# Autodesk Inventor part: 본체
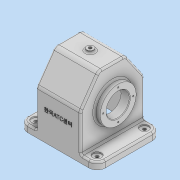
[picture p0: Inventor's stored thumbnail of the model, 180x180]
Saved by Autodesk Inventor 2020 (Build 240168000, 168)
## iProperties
Created: 2022-12
Part Number: 본체
Material: 일반
Document SubType Name: Modeling
Designer: 1강의실14
Density: 1 g/cm^3
Appearance: 기본값
Mass: 347.033 g
Surface Area: 1065.53 cm^2
Volume: 347.033 cm^3
Author: 1강의실14
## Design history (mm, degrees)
sketch "스케치1"
  geometry: L1 (67, -55)-(-67, -55); L2 (-67, -55)-(-67, 55); L3 (-67, 55)-(67, 55); L4 (67, 55)-(67, -55); L5 (67, -55)-(-67, 55); L6 (-67, -55)-(67, 55); 1 further point
  constraints: 12 end point, 2 midpoint, 2 parallel, 1 horizontal, 1 perpendicular
  dimensions: "d0" = 134 distance of L2.end L3.end; "d1" = 110 distance of L1.end L2.end
extrude "돌출1" new body sketch "스케치1" distance "d2" = 12; taper "d3" = 0 deg
fillet "모깎기1" dims "d4" = 14
sketch "스케치2"
  geometry: A1 r 14 centre (-53, -41) between (-67, -41) and (-53, -55) reference; A2 r 14 centre (-53, 41) between (-53, 55) and (-67, 41) reference; A3 r 14 centre (53, -41) between (53, -55) and (67, -41) reference; A4 r 14 centre (53, 41) between (67, 41) and (53, 55) reference; 5 further points
  constraints: 4 coincident
hole "구멍1" sketch "스케치2" at (-53, -41), (-53, 41), (53, -41), (53, 41) diameter "d5" = 5.5; stored, may be unused: countersink angle "d9" = 90 deg, drill point angle "d11" = 118 deg; dims "d6" = 30, "d7" = 15, "d8" = 2, "d10" = 8
sketch "스케치3"
  geometry: L1 (55, 0)-(55, 12) reference; L2 (-55, 12)-(-55, 0) reference; L3 (55, 12)-(55, 77); L4 (55, 77)-(23.491, 122); L5 (23.491, 122)-(-23.491, 122); L6 (-23.491, 122)-(-55, 77); L7 (-55, 77)-(-55, 12); L8 (0, 122)-(0, 0); L9 (-41, 12)-(41, 12) reference; L10 (33.5, 12)-(48.5, 12) reference; L11 (41, 12)-(55, 12) reference; L12 (-48.5, 12)-(-33.5, 12) reference; L13 (-48.5, 12)-(-33.5, 12) reference; L14 (33.5, 12)-(48.5, 12) reference; L15 (33.5, 12)-(48.5, 12) reference; L16 (-41, 12)-(-55, 12) reference; L17 (-41, 12)-(41, 12) reference; L18 (55, 12)-(41, 12) reference; L19 (41, 12)-(55, 12) reference; L20 (41, 12)-(-41, 12) reference; L21 (-55, 12)-(-41, 12) reference; 3 further points
  constraints: 12 end point, 2 vertical, 1 midpoint, 1 parallel, 1 perpendicular, 1 vertical alignment, 1 other
  dimensions: "d12" = 35 deg angle of L4 L3; "d13" = 122 distance from line of L5 L1.start; "d14" = 77 distance of L1.start L3.end
extrude "돌출2" join sketch "스케치3" stored distance "d15" = 77; taper "d16" = 0 deg
sketch "스케치4"
  geometry: L1 (-55, 12)-(-55, 0) reference; L2 (-55, 77)-(-55, 12) reference; L3 (-55, 12)-(-55, 77) reference; L4 (-55, 0)-(-55, 12) reference; L5 (-23.491, 122)-(-55, 77) reference; L6 (-55, 77)-(-23.491, 122) reference; L7 (23.491, 122)-(-23.491, 122) reference; L8 (-23.491, 122)-(23.491, 122) reference; L9 (55, 77)-(23.491, 122) reference; L10 (23.491, 122)-(55, 77) reference; L11 (55, 0)-(55, 12) reference; L12 (55, 12)-(55, 0) reference; L13 (55, 77)-(55, 12) reference; L14 (55, 12)-(55, 77) reference; L15 (55, 0)-(41, 0) reference; L16 (50, 0)-(50, 75.424); L17 (50, 75.424)-(20.888, 117); L18 (20.888, 117)-(-20.888, 117); L19 (-20.888, 117)-(-50, 75.424); L20 (-50, 75.424)-(-50, 0); L21 (-41, 0)-(-55, 0) reference; L22 (50, 0)-(-41, 0); 2 further points
  constraints: 12 end point, 4 parallel, 1 horizontal, 1 horizontal alignment, 1 perpendicular, 1 point on line, 1 vertical
  dimensions: "d17" = 5 distance between parallel lines of L16 L13; "d18" = 5 distance between parallel lines of L2 L20; "d19" = 5 distance between parallel lines of L7 L18; "d20" = 5 distance between parallel lines of L5 L19; "d21" = 5 distance between parallel lines of L17 L9
extrude "돌출3" cut sketch "스케치4" stored distance "d22" = 67; taper "d23" = 0 deg
sketch "스케치5"
  geometry: L1 (33.5, 75.424)-(33.5, 117) reference; L2 (33.5, 0)-(33.5, 75.424) reference; L3 (33.5, 75.424)-(33.5, 0) reference; L4 (33.5, 117)-(33.5, 75.424) reference; L5 (33.5, 75.424)-(33.5, 0) reference; L6 (19.5, 65)-(19.5, 92); L7 (19.5, 92)-(33.5, 106); L8 (43.5, 65)-(-48.5, 65); L9 (38.5, 122)-(38.5, 77) reference; L10 (38.5, 12)-(38.5, 77) reference; L11 (38.5, 77)-(38.5, 122) reference; L12 (38.5, 122)-(38.5, 77) reference; L13 (38.5, 77)-(38.5, 12) reference; L14 (-38.5, 12)-(-38.5, 77) reference; L15 (-38.5, 77)-(-38.5, 122) reference; L16 (-38.5, 122)-(-38.5, 77) reference; L17 (-38.5, 77)-(-38.5, 12) reference; L18 (38.5, 102.5)-(43.5, 102.5); L19 (43.5, 102.5)-(43.5, 65); L20 (-48.5, 65)-(-48.5, 96); L21 (-48.5, 96)-(-38.5, 96); 8 further points
  constraints: 14 end point, 4 point on line, 3 perpendicular, 2 vertical, 1 horizontal
  dimensions: "d24" = 135 deg angle of L7 L1; "d27" = 65 vertical distance of L8.start L2.start; "d28" = 5 distance of L18.start L18.end; "d29" = 75 diameter of L18 L8; "d30" = 54 diameter of L6.end L8; "d31" = 10 distance of L20.end L21.end; "d32" = 62 diameter of L21 L8; "d87" = 24 distance between parallel lines of L6 L19
revolve "회전1" sketch "스케치5" stored, may be unused: angle "d34" = 90 deg
sketch "스케치6"
  geometry: C1 r 31 at (0, 0) reference; 2 further points
  constraints: 1 coincident
hole "구멍2" sketch "스케치6" at (0, 0) diameter "d35" = 40; stored, may be unused: countersink angle "d39" = 90 deg, drill point angle "d41" = 118 deg; dims "d36" = 30, "d37" = 15, "d38" = 2, "d40" = 8
node "작업 평면1"
sketch "스케치7"
  geometry: C1 r 6 at (38.5, 23.491); 1 further point
  constraints: 1 centre point, 1 coincident
  dimensions: "d43" = 12 diameter of C1
extrude "돌출4" join sketch "스케치7" stored distance "d44" = 67; taper "d45" = 0 deg
sketch "스케치8"
  geometry: C1 r 6 at (0, 0) reference; 2 further points
  constraints: 1 coincident
hole "구멍3" sketch "스케치8" at (0, 0) diameter "d46" = 5.1881; stored, may be unused: countersink angle "d50" = 90 deg, drill point angle "d52" = 118 deg; dims "d47" = 12, "d48" = 15, "d49" = 2, "d51" = 16
sketch "스케치9" dims "d53" = 52
  geometry: L1 (0, 0)-(-26, 0); C1 r 31 at (0, 0) reference; C2 r 31 at (0, 0) reference; 2 further points
  constraints: 2 end point, 1 coincident, 1 horizontal, 1 horizontal alignment, 2 other
hole "구멍4" sketch "스케치9" at (-26, 0) diameter "d54" = 2.459; stored, may be unused: countersink angle "d58" = 90 deg, drill point angle "d60" = 118 deg; dims "d55" = 6, "d56" = 15, "d57" = 2, "d59" = 8
sketch "스케치10" dims "d64" = 58
  geometry: L1 (0, 0)-(29, 0); C1 r 37.5 at (0, 0) reference; 1 further point
  constraints: 2 end point, 1 coincident, 1 horizontal, 1 horizontal alignment, 2 other
hole "구멍5" sketch "스케치10" at (29, 0) diameter "d65" = 2.459; stored, may be unused: countersink angle "d69" = 90 deg, drill point angle "d71" = 118 deg; dims "d66" = 6, "d67" = 15, "d68" = 2, "d70" = 8
fillet "모깎기2" dims "d75" = 10
chamfer "모따기1" distance "d76" = 1; stored, may be unused: second distance "d77" = 2, angle "d78" = 45 deg
fillet "모깎기3" dims "d79" = 3
fillet "모깎기4" dims "d80" = 3
fillet "모깎기5" dims "d81" = 3
fillet "모깎기6" dims "d82" = 3
sketch "스케치11" dims "d0" = 134, "d1" = 110
  geometry: L1 (14.5, 73.847)-(14.5, 15) reference; L2 (0, 0)-(106, 0) reference; 2 further points
  constraints: 1 other
  dimensions: "d83" = 38.5 distance from line of point (53, 50) L1; "d84" = 50 distance from line of point (53, 50) L2
feature "엠보싱1" sketch "스케치11" dims "d0" = 134, "d1" = 110, "d85" = 0.5, "d86" = 0
node "솔리드1"
pattern_circular "원형 패턴1" dims angle "d62" = 360 deg
pattern_circular "원형 패턴2" dims angle "d73" = 360 deg
node "투영된 루프1"
node "투영된 루프2"
node "투영된 루프3"
node "투영된 루프4"
node "투영된 루프5"
node "투영된 루프6"
node "투영된 루프7"
node "투영된 루프8"
node "투영된 루프9"
feature "A9D066F2-1C7D-4E18-AEED-F7BC21143FA4" dims "d5" = 5.5, "d6" = 30, "d7" = 15, "d8" = 2, "d9" = 90 deg, "d10" = 8, "d11" = 118 deg
other parameters: "d42" = 4
